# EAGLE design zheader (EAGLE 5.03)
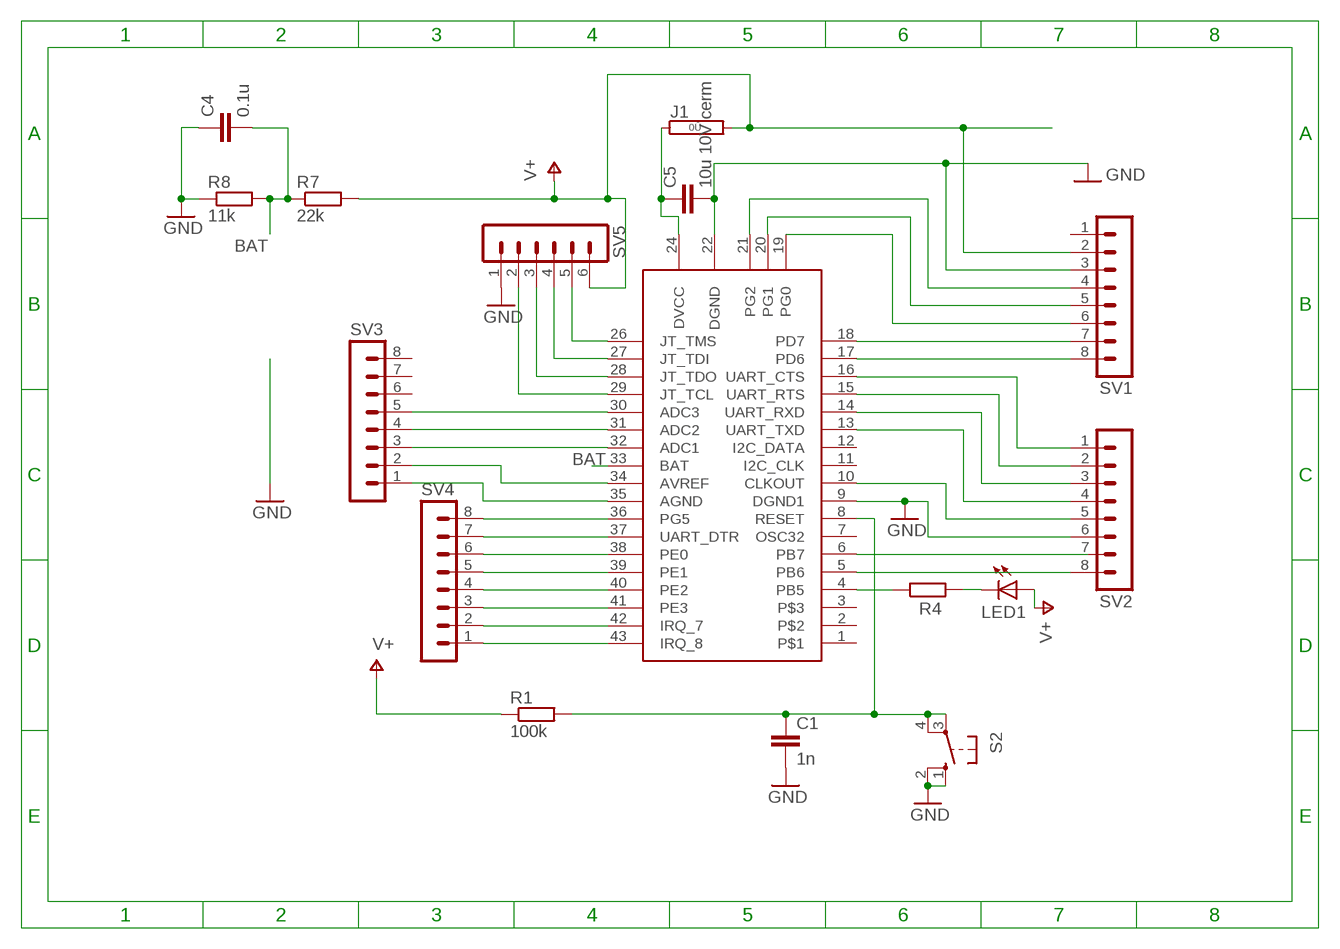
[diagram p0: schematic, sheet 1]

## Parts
C1  1n  C2.5P  [C025-030X050]
C4  0.1u  C5P  [C050-030-075]
C5  10u 10V cerm  CSMT0805  [C0805]
J1  0R  [0R/10]
LED1  LED-3MM3MM  [HLMP-D105]
R1  100k  R  [0207/10]
R4  470  R  [0207/10]
R7  22k  R  [0207/10]
R8  11k  R  [0207/10]
S2  10-XX  [B3F-10XX]
SV1  MA08-1  [MA08-1]
SV2  MA08-1  [MA08-1]
SV3  MA08-1  [MA08-1]
SV4  MA08-1  [MA08-1]
SV5  MA06-1  [MA06-1]
U$1  ZDM-A1281-A2N  [ZIGSMD]

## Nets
BAT: C4.2 R7.1 R8.2 U$1.33(BAT)
GND [supply]: C1.2 C4.1 C5.2 R8.1 S2.1(S) S2.2(S1) SV1.3 SV2.6 SV5.1 U$1.9(DGND1) U$1.22(DGND)
N$1: SV1.6 U$1.19(PG0)
N$2: SV2.1 U$1.16(UART_CTS)
N$3: SV2.2 U$1.15(UART_RTS)
N$4: SV2.5 U$1.10(CLKOUT)
N$5: SV2.4 U$1.13(UART_TXD)
N$6: SV2.3 U$1.14(UART_RXD)
N$7: SV1.8 U$1.17(PD6)
N$8: LED1.K(C) R4.2
N$9: U$1.6(PB7)
N$10: SV1.7 U$1.18(PD7)
N$11: SV1.5 U$1.20(PG1)
N$12: SV1.4 U$1.21(PG2)
N$13: C1.1 R1.2 S2.3(P) S2.4(P1) U$1.8(RESET)
N$14: SV2.8 U$1.5(PB6)
N$15: R4.1 U$1.4(PB5)
N$16: SV4.1 U$1.43(IRQ_8)
N$17: SV4.2 U$1.42(IRQ_7)
N$18: SV4.3 U$1.41(PE3)
N$19: SV4.4 U$1.40(PE2)
N$20: SV4.5 U$1.39(PE1)
N$21: SV4.6 U$1.38(PE0)
N$22: SV4.7 U$1.37(UART_DTR)
N$23: SV4.8 U$1.36(PG5)
N$24: SV3.2 U$1.34(AVREF)
N$25: SV3.3 U$1.32(ADC1)
N$26: SV3.4 U$1.31(ADC2)
N$27: SV3.5 U$1.30(ADC3)
N$28: SV5.2 U$1.29(JT_TCL)
N$29: SV5.3 U$1.28(JT_TDO)
N$30: SV5.4 U$1.27(JT_TDI)
N$31 [supply]: C5.1 J1.1 U$1.24(DVCC)
N$32: SV5.5 U$1.26(JT_TMS)
N$34 [supply]: SV3.1 U$1.35(AGND)
V+: J1.2 LED1.A R1.1 R7.2 SV1.2 SV5.6
Unconnected: SV1.1 SV2.7 SV3.6 SV3.7 SV3.8 U$1.1 U$1.2 U$1.3 U$1.7(OSC32) U$1.11(I2C_CLK) U$1.12(I2C_DATA)

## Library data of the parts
C1 C4 C5 = ee2parts:C: Capacitor
J1 = jumper:0R: Bridge 0R 10mm
LED1 = ee2parts:LED-3MM: LED
R1 R4 R7 R8 = ee2parts:R: Resistor
S2 = switch-omron:10-XX: OMRON SWITCH
SV1-SV4 = con-lstb:MA08-1: PIN HEADER
SV5 = con-lstb:MA06-1: PIN HEADER
U$1 = 0Zigbit:ZDM-A1281-A2

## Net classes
1 supply: width 0.508 mm

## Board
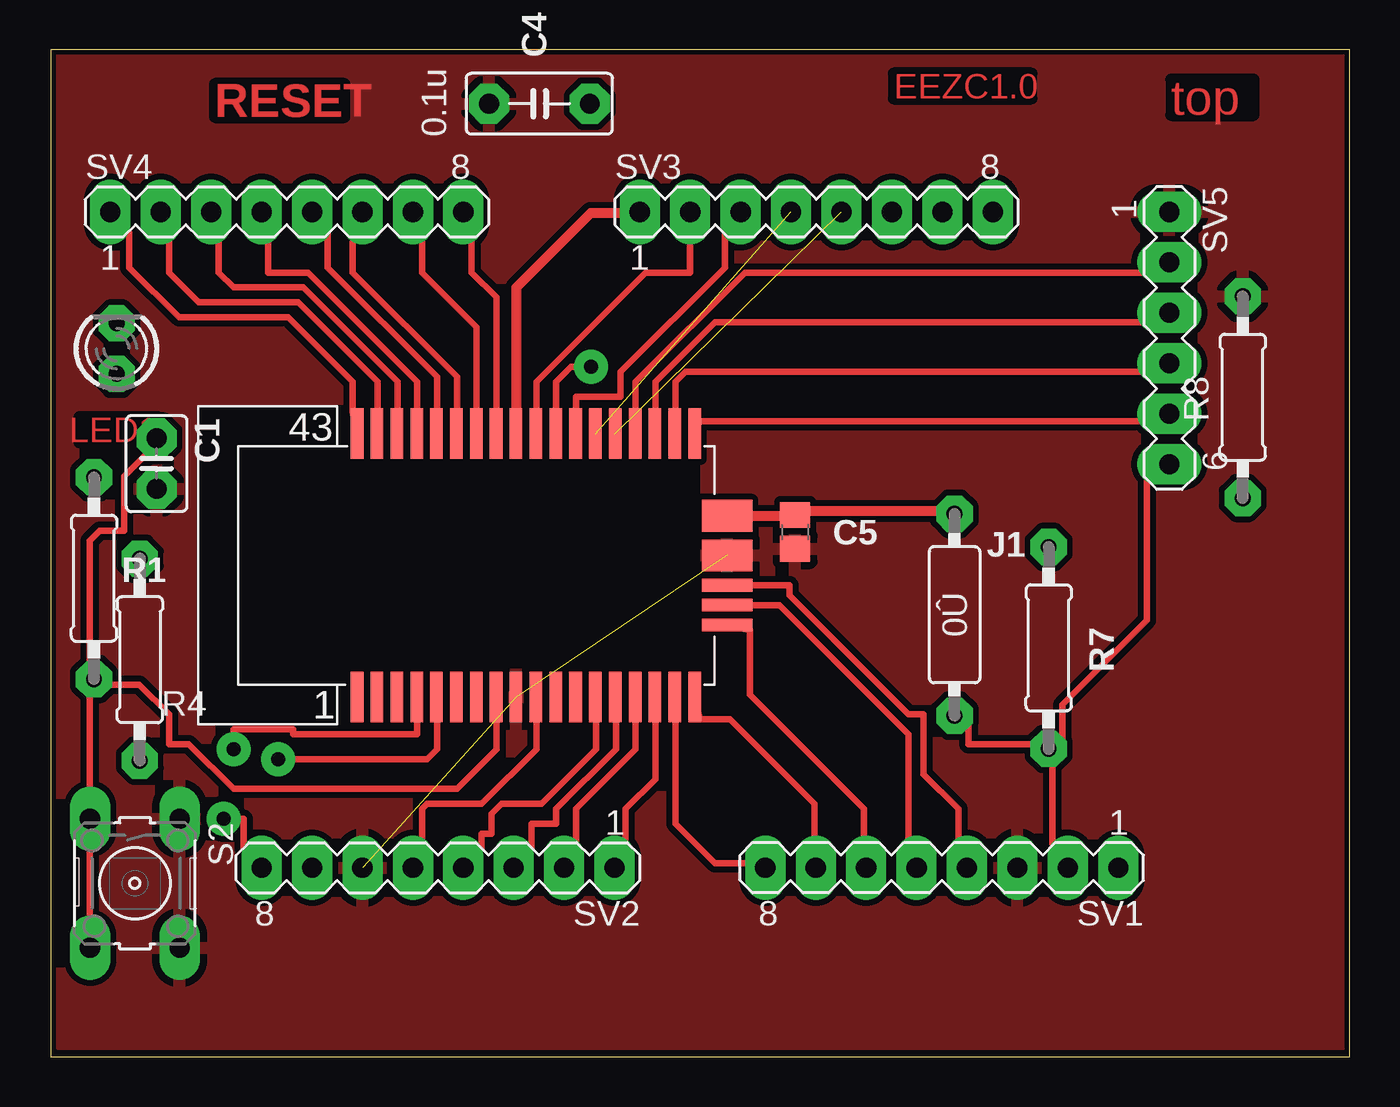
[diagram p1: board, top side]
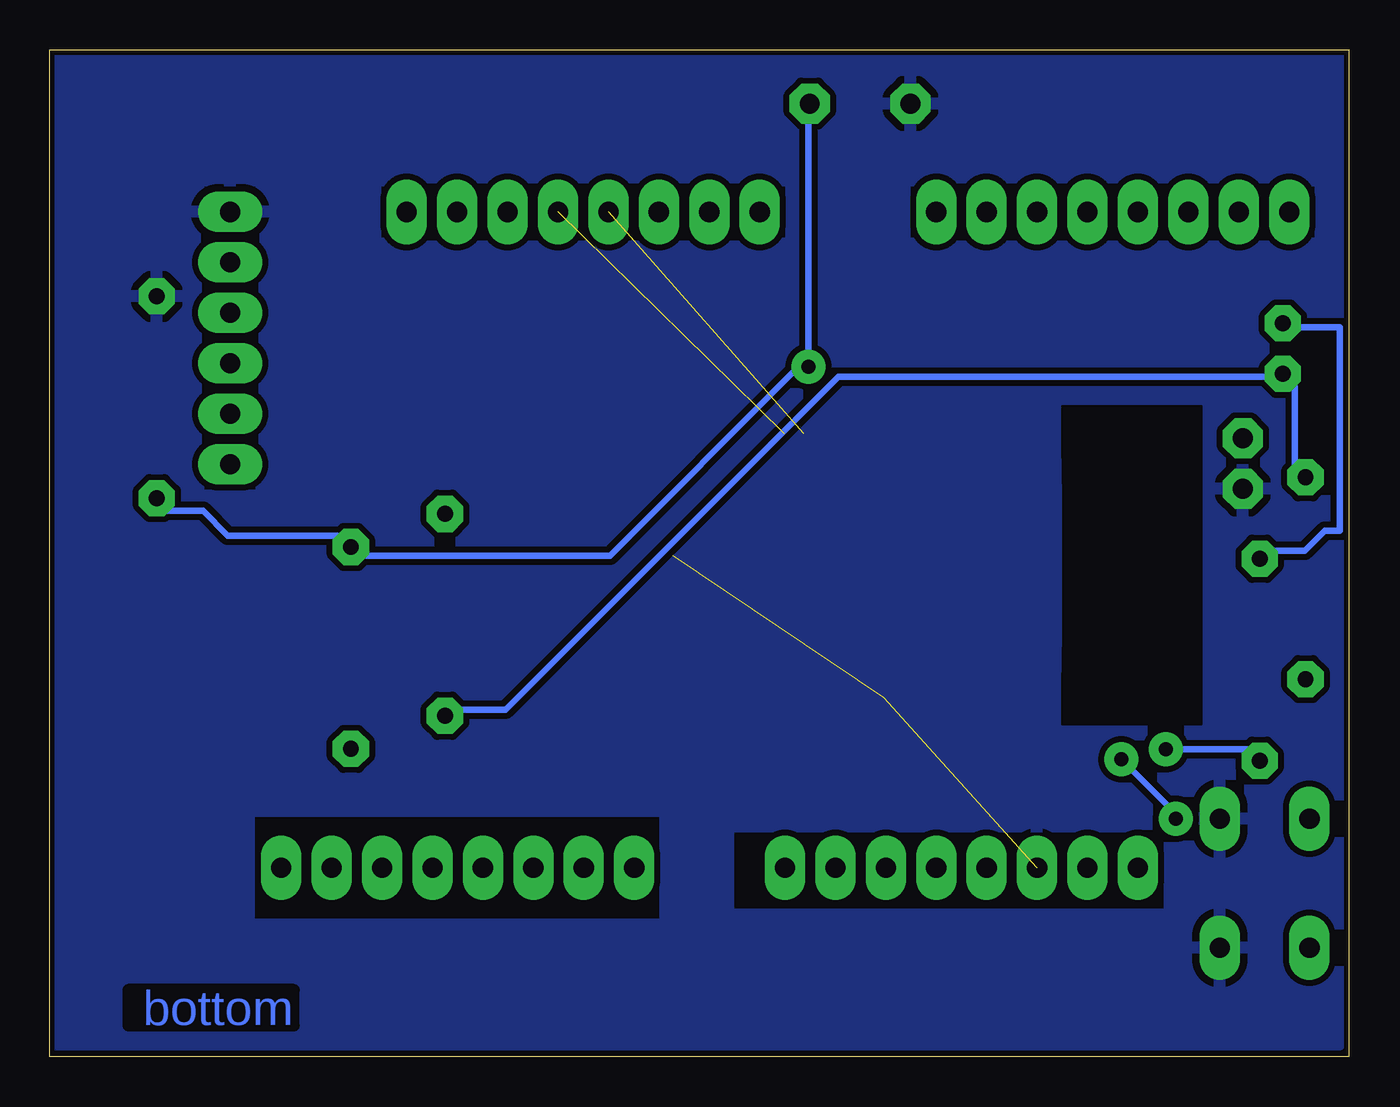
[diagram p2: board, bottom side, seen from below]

Size 65.44 x 50.71 mm. Coordinates in mm from the lower left corner, seen from the top.
Outline: 0,0 65.44,0 65.44,50.71 0,50.71 0,0
Copper layers (1*16): Top 0.035mm / dielectric 1.5mm / Bottom 0.035mm
Design rules "zigbit_rules *": minimum track width 13mil, minimum drill 0.7mm, track to track 12mil, track to pad 13mil, pad to pad 13mil, via to via 13mil, smd to smd 0mil, copper to edge 10mil, drill to drill 10mil, minimum pad ring 20mil, minimum via ring 20mil, stop-mask expansion 0mil, vias tented up to drill 0mil, thermal gap 15mil
bRestrict: area 1.7,41.3 to 22.1,43.8; area 28.4,41.3 to 48.7,43.8; area 9.4,7.5 to 31,11.3; area 34.8,7 to 55.1,12.1; area 55.1,28.6 to 57.6,43.8
vRestrict: area 13.2,12.1 to 37.3,17.1

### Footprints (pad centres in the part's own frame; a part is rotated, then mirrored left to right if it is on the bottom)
C025-030X050 = drill 1 octagon: 1 -1.27,0; 2 1.27,0
C050-030-075 = drill 1 octagon: 1 -2.54,0; 2 2.54,0
C0805 = smd 1.3 x 1.5: 1 -0.85,0; 2 0.85,0
0R/10 = drill 0.813 pad 1.6 octagon: 1 -5.08,0; 2 5.08,0
HLMP-D105 = drill 0.8 octagon: A -1.27,0; K 1.27,0
0207/10 = drill 0.8 octagon: 1 -5.08,0; 2 5.08,0
B3F-10XX = drill 1.016 long: 1 -3.251,2.261; 2 3.251,2.261; 3 -3.251,-2.261; 4 3.251,-2.261
MA08-1 = drill 1.016 long: 1 -8.89,0; 2 -6.35,0; 3 -3.81,0; 4 -1.27,0; 5 1.27,0; 6 3.81,0; 7 6.35,0; 8 8.89,0
MA06-1 = drill 1.016 long: 1 -6.35,0; 2 -3.81,0; 3 -1.27,0; 4 1.27,0; 5 3.81,0; 6 6.35,0
ZIGSMD = smd 0.635 x 2.54: 1 7,6.635; 2 6,6.635; 3 5,6.635; 4 4,6.635; 5 3,6.635; 6 2,6.635; 7 1,6.635; 8 0,6.635; 9 -1,6.635; 10 -2,6.635; 11 -3,6.635; 12 -4,6.635; 13 -5,6.635; 14 -6,6.635; 15 -7,6.635; 16 -8,6.635; 17 -9,6.635; 18 -10,6.635; 26 -10,-6.635; 27 -9,-6.635; 28 -8,-6.635; 29 -7,-6.635; 30 -6,-6.635; 31 -5,-6.635; 32 -4,-6.635; 33 -3,-6.635; 34 -2,-6.635; 35 -1,-6.635; 36 0,-6.635; 37 1,-6.635; 38 2,-6.635; 39 3,-6.635; 40 4,-6.635; 41 5,-6.635; 42 6,-6.635; 43 7,-6.635 | smd 2.54 x 0.635: 19 -11.635,3; 20 -11.635,2; 21 -11.635,1 | smd 2.54 x 1.6: 22 -11.635,-0.5; 24 -11.635,-2.5

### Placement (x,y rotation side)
C1  5.34,29.87 270 top
C4  24.62,47.99 0 top
C5  37.5,26.43 270 top
J1  45.53,22.26 270 top
LED1  3.33,35.66 90 top
R1  2.19,24.1 270 top
R4  4.5,20 90 top
R7  50.27,20.59 270 top
R8  60.04,33.21 270 top
S2  4.25,8.74 270 top
SV1  44.89,9.53 180 top
SV2  19.52,9.52 180 top
SV3  38.57,42.54 0 top
SV4  11.9,42.54 0 top
SV5  56.35,36.19 270 top
U$1  22.44,24.75 180 top

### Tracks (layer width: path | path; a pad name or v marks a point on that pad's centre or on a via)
BAT  (via drill 0.7)
  Top 0.33: v27.22,34.74 26.22,34.74 25.47,33.99 25.47,32.49 U$1.33
  Bottom 0.33: R8.2 59.47,27.49 57.72,27.49 56.47,26.24 50.97,26.24 R7.1 49.47,25.24 37.22,25.24 27.97,34.49 v27.22,34.74 27.22,46.99 C4.2
GND  (2 unrouted)
  pour Bottom: 0.47,50.36 65.28,50.36 65.28,0.63 0.47,0.63
  pour Top: 0.47,50.36 65.28,50.36 65.28,0.63 0.47,0.63
N$1
  Top 0.33: U$1.19 35.22,21.49 35.22,18.24 40.97,12.49 40.97,10.99 SV1.6
N$2
  Top 0.33: U$1.16 30.47,16.99 30.47,13.99 28.97,12.49 28.97,10.99 SV2.1
N$3
  Top 0.33: U$1.15 29.47,16.99 29.47,15.49 26.47,12.49 26.47,10.74 SV2.2
N$4
  Top 0.33: U$1.10 24.47,16.99 24.47,15.49 21.72,12.74 18.97,12.74 18.72,12.49 18.72,10.99 SV2.5
N$5
  Top 0.33: U$1.13 27.47,16.99 27.47,15.49 24.72,12.74 22.72,12.74 22.22,12.24 22.22,11.24 21.72,11.24 21.72,10.49 SV2.4
N$6
  Top 0.33: U$1.14 28.47,16.99 28.47,15.49 25.47,12.49 25.47,11.74 24.22,11.74 24.22,10.49 SV2.3
N$7
  Top 0.33: U$1.17 31.47,16.99 31.47,11.74 33.47,9.74 35.22,9.74 SV1.8
N$8
  Bottom 0.33: R4.2 3.72,25.49 2.22,25.49 1.22,26.49 0.47,26.49 0.47,36.74 2.47,36.74 LED1.K
N$10
  Top 0.33: U$1.18 32.72,16.99 34.22,16.99 38.47,12.74 38.47,10.99 SV1.7
N$11
  Top 0.33: U$1.20 35.22,22.74 36.72,22.74 43.22,16.24 43.22,10.99 SV1.5
N$12
  Top 0.33: U$1.21 35.22,23.74 37.22,23.74 37.22,23.24 43.22,17.24 43.97,17.24 43.97,14.24 45.72,12.49 45.72,10.99 SV1.4
N$13
  Top 0.33: S2.4 1.97,6.99 1.97,10.49 S2.3 1.97,13.49 1.97,18.24 R1.2 | U$1.8 22.47,16.99 22.47,15.49 20.47,13.49 9.22,13.49 6.97,15.74 5.97,15.74 5.97,17.24 4.47,18.74 2.97,18.74 R1.2 | C1.1 4.97,30.24 4.72,30.24 3.72,29.24 3.72,26.49 2.47,26.49 1.97,25.99 1.97,19.74 R1.2
N$14  (via drill 0.7)
  Top 0.33: v11.47,14.99 18.97,14.99 19.47,15.49 19.47,16.99 U$1.5 | v8.72,11.99 9.72,11.99 9.72,10.49 SV2.8
  Bottom 0.33: v11.47,14.99 8.97,12.49 8.97,11.99 v8.72,11.99
N$15  (via drill 0.7)
  Top 0.33: v9.22,15.49 9.22,16.49 12.22,16.49 12.22,16.24 18.47,16.24 18.47,16.99 U$1.4
  Bottom 0.33: v9.22,15.49 4.97,15.49 R4.1
N$16
  Top 0.33: U$1.43 15.22,32.49 15.22,33.99 11.97,37.24 6.47,37.24 3.97,39.74 3.97,41.49 SV4.1
N$17
  Top 0.33: U$1.42 16.47,32.49 16.47,33.99 12.47,37.99 7.47,37.99 5.97,39.49 5.97,40.99 SV4.2
N$18
  Top 0.33: U$1.41 17.47,32.49 17.47,33.99 12.72,38.74 9.22,38.74 8.47,39.49 8.47,40.99 SV4.3
N$19
  Top 0.33: U$1.40 18.47,32.49 18.47,33.99 12.97,39.49 10.97,39.49 10.97,40.99 SV4.4
N$20
  Top 0.33: U$1.39 19.47,32.49 19.47,34.24 13.97,39.74 13.97,41.49 SV4.5
N$21
  Top 0.33: U$1.38 20.47,32.49 20.47,34.24 15.22,39.49 15.22,40.99 SV4.6
N$22
  Top 0.33: U$1.37 21.47,32.49 21.47,36.74 18.72,39.49 18.72,40.99 SV4.7
N$23
  Top 0.33: U$1.36 22.47,32.49 22.47,38.24 21.22,39.49 21.22,40.99 SV4.8
N$24
  Top 0.33: U$1.34 24.47,32.49 24.47,33.99 29.97,39.49 32.22,39.49 SV3.2
N$25
  Top 0.33: U$1.32 26.47,32.49 26.47,33.24 28.72,33.24 28.72,34.49 33.97,39.74 33.97,41.49 SV3.3
N$26  (1 unrouted)
N$27  (1 unrouted)
N$28
  Top 0.33: U$1.29 29.47,32.49 29.47,33.99 34.97,39.49 54.97,39.49 SV5.2
N$29
  Top 0.33: U$1.28 30.47,32.49 30.47,33.99 33.47,36.99 54.97,36.99 SV5.3
N$30
  Top 0.33: U$1.27 31.47,32.49 31.47,33.99 31.97,34.49 54.97,34.49 SV5.4
N$31
  Top 0.508: U$1.24 35.22,27.24 36.97,27.24 C5.1 38.22,27.49 44.72,27.49 J1.1
N$32
  Top 0.33: U$1.26 32.72,31.99 54.97,31.99 SV5.5
N$34
  Top 0.508: U$1.35 23.47,32.49 23.47,38.74 27.22,42.49 28.72,42.49 SV3.1
V+
  Top 0.33: R7.2 50.47,14.74 50.47,10.74 SV1.2 | J1.2 46.22,16.74 46.22,15.74 49.47,15.74 R7.2 | SV5.6 55.22,28.99 55.22,21.99 50.97,17.74 50.97,15.99 R7.2
  Bottom 0.33: R1.1 2.72,29.74 2.72,33.74 LED1.A 4.22,34.24 25.72,34.24 42.47,17.49 44.72,17.49 J1.2

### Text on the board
Top: RESET | EEZC1.0 | top
Bottom: bottom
